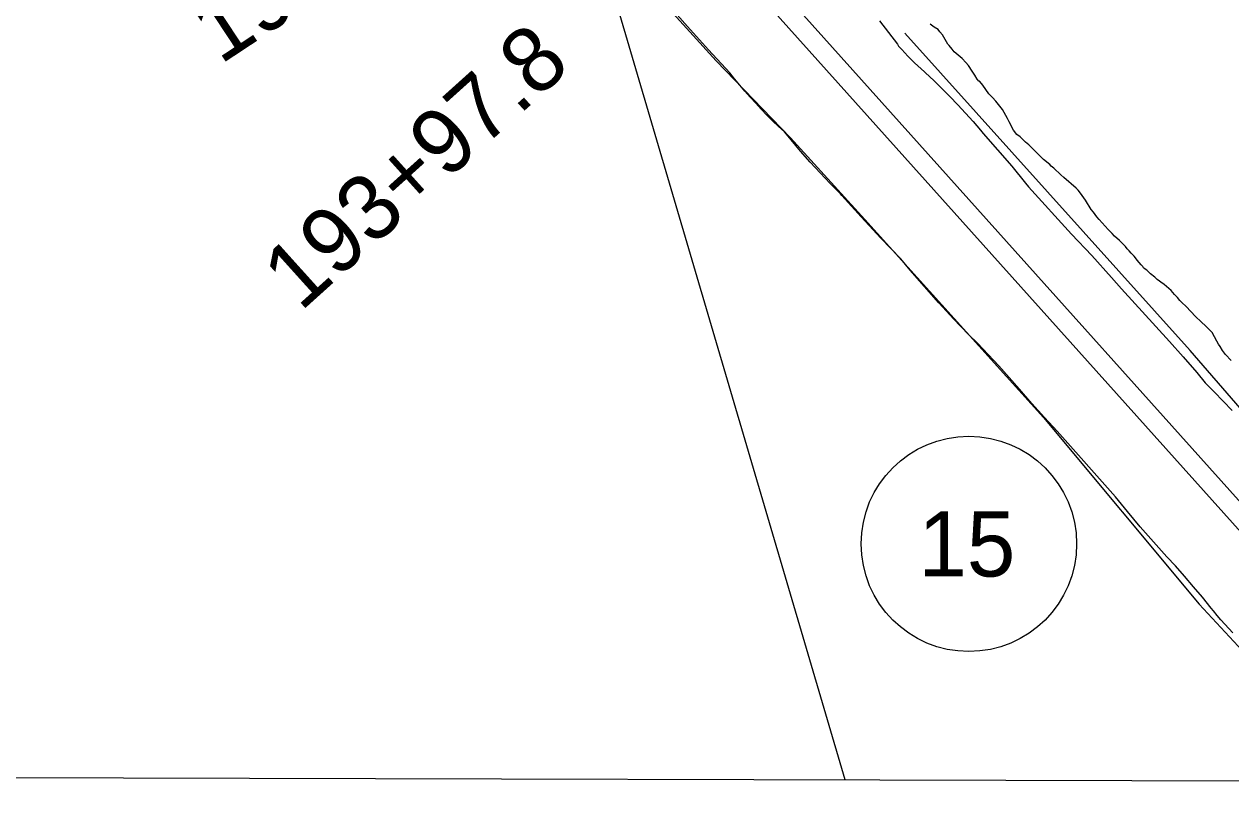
# Model space of a CAD drawing. Extents: x 3172231 to 3210228, y 940198 to 965780.
# Drawn here: x 3188013 to 3189862, y 945652 to 946857 of the extents above; entities that cross this region are included whole.
import ezdxf

# ---------------------------------------------------------------- set-up
doc = ezdxf.new("R2010")
doc.units = 0
for name, color, linetype in [('V-GRID-FRAM', 7, 'Continuous'), ('V-LEVE-TOET', 7, 'Continuous'), ('V-ROAD-IDEN', 7, 'Continuous'), ('V-SITE-VEGE', 7, 'Continuous'), ('V-SURV-IDEN', 7, 'Continuous'), ('V-SURV-LINE', 7, 'Continuous'), ('V-TOPO-BNDY', 7, 'Continuous'), ('V-TOPO-SHOR', 7, 'Continuous')]:
    doc.layers.add(name, color=color, linetype=linetype)

msp = doc.modelspace()

# ---------------------------------------------------------------- linework, layer by layer
at = {"layer": 'V-GRID-FRAM'}
msp.add_lwpolyline([(3176539.592, 963919.479), (3207827.662, 963842.116), (3207790.623, 945652.442), (3176486.679, 945729.845), (3176539.592, 963919.479)], dxfattribs=at)
at = {"layer": 'V-LEVE-TOET'}
for points in [[(3189865.016, 945923.694), (3189858.825, 945930.252), (3189852.751, 945936.916), (3189846.795, 945943.684), (3189840.956, 945950.556), (3189835.238, 945957.527), (3189831.896, 945961.721), (3189831.896, 945961.721), (3189818.602, 945978.21), (3189805.024, 945994.463), (3189791.165, 946010.478), (3189777.028, 946026.248), (3189763.816, 946040.502), (3189763.816, 946040.502), (3189743.297, 946063.247), (3189723.176, 946086.346), (3189703.458, 946109.79), (3189685.284, 946132.156), (3189685.284, 946132.156), (3189595.733, 946232.725), (3189595.733, 946232.725), (3189576.504, 946254.049), (3189557.261, 946275.497), (3189538.072, 946296.991), (3189538.072, 946296.991), (3189522.415, 946315.061), (3189506.457, 946332.864), (3189490.197, 946350.395), (3189473.646, 946367.647), (3189460.297, 946381.145), (3189460.297, 946381.145), (3189437.312, 946405.177), (3189414.749, 946429.605), (3189392.614, 946454.423), (3189370.914, 946479.621), (3189356.371, 946497.017), (3189356.371, 946497.017), (3189325.692, 946528.792), (3189295.57, 946561.099), (3189266.019, 946593.924), (3189263.754, 946596.489), (3189263.754, 946596.489), (3189248.071, 946612.514), (3189232.668, 946628.814), (3189217.553, 946645.378), (3189202.728, 946662.203), (3189188.199, 946679.285), (3189178.052, 946691.585), (3189178.052, 946691.585), (3189168.942, 946700.019), (3189159.982, 946708.61), (3189151.172, 946717.357), (3189142.517, 946726.256), (3189134.017, 946735.304), (3189125.678, 946744.5), (3189117.5, 946753.838), (3189109.487, 946763.319), (3189101.639, 946772.938), (3189094.348, 946782.193), (3189094.348, 946782.193), (3189061.516, 946817.458), (3189029.289, 946853.275), (3189013.872, 946870.853)], [(3189323.783, 946861.932), (3189337.523, 946843.893), (3189351.112, 946825.731), (3189353.043, 946823.122), (3189353.043, 946823.122), (3189357.684, 946817.861), (3189362.412, 946812.677), (3189367.231, 946807.576), (3189372.134, 946802.554), (3189377.123, 946797.616), (3189382.194, 946792.765), (3189387.347, 946787.999), (3189392.58, 946783.321), (3189394.173, 946781.929), (3189394.173, 946781.929), (3189406.838, 946770.052), (3189419.294, 946757.957), (3189431.539, 946745.648), (3189443.567, 946733.127), (3189455.375, 946720.399), (3189466.961, 946707.468), (3189478.319, 946694.336), (3189482.737, 946689.103), (3189482.737, 946689.103), (3189504.712, 946664.157), (3189526.257, 946638.837), (3189547.363, 946613.151), (3189551.916, 946607.49), (3189551.916, 946607.49), (3189617.8, 946534.844), (3189617.8, 946534.844), (3189648.793, 946501.891), (3189679.205, 946468.405), (3189694.645, 946450.945), (3189694.645, 946450.945), (3189746.851, 946393.356), (3189746.851, 946393.356), (3189768.199, 946370.18), (3189789.144, 946346.641), (3189809.679, 946322.743), (3189822.707, 946307.143), (3189822.707, 946307.143), (3189836.649, 946293.081), (3189850.432, 946278.86), (3189864.048, 946264.479)]]:
    msp.add_lwpolyline(points, dxfattribs=at)
at = {"layer": 'V-ROAD-IDEN'}
msp.add_circle((3189460.656, 946060.116), 165, dxfattribs=at)
at = {"layer": 'V-SITE-VEGE'}
for p, q in [((3189407.581, 946852.134), (3189401.085, 946856.689)), ((3189413.363, 946848.329), (3189407.581, 946852.134)), ((3189416.22, 946844.962), (3189413.363, 946848.329)), ((3189420.142, 946840.098), (3189416.22, 946844.962)), ((3189428.614, 946825.959), (3189420.142, 946840.098)), ((3189430.404, 946824.081), (3189428.614, 946825.959)), ((3189435.033, 946818.103), (3189430.404, 946824.081)), ((3189438.248, 946814.359), (3189435.033, 946818.103)), ((3189450.114, 946804.172), (3189438.248, 946814.359)), ((3189456.203, 946797.793), (3189450.114, 946804.172)), ((3189460.133, 946793.297), (3189456.203, 946797.793)), ((3189465.802, 946784.726), (3189460.133, 946793.297)), ((3189469.689, 946778.398), (3189465.802, 946784.726)), ((3189473.584, 946772.438), (3189469.689, 946778.398)), ((3189476.083, 946769.442), (3189473.584, 946772.438)), ((3189476.806, 946769.057), (3189476.083, 946769.442)), ((3189480.029, 946765.68), (3189476.806, 946769.057)), ((3189481.805, 946763.071), (3189480.029, 946765.68)), ((3189491.402, 946750.005), (3189481.805, 946763.071)), ((3189496.772, 946744.377), (3189491.402, 946750.005)), ((3189501.769, 946738.386), (3189496.772, 946744.377)), ((3189512.109, 946725.668), (3189501.769, 946738.386)), ((3189517.401, 946716.741), (3189512.109, 946725.668)), ((3189519.867, 946712.278), (3189517.401, 946716.741)), ((3189522.312, 946707.085), (3189519.867, 946712.278)), ((3189528.976, 946694.086), (3189522.312, 946707.085)), ((3189533.963, 946687.733), (3189528.976, 946694.086)), ((3189539.012, 946683.946), (3189533.963, 946687.733)), ((3189547.623, 946675.672), (3189539.012, 946683.946)), ((3189552.661, 946671.517), (3189547.623, 946675.672)), ((3189561.621, 946662.502), (3189552.661, 946671.517)), ((3189567.708, 946656.12), (3189561.621, 946662.502)), ((3189574.888, 946649.349), (3189567.708, 946656.12)), ((3189584.606, 946641.416), (3189574.888, 946649.349)), ((3189586.757, 946639.165), (3189584.606, 946641.416)), ((3189590.719, 946636.136), (3189586.757, 946639.165)), ((3189601.48, 946625.609), (3189590.719, 946636.136)), ((3189606.159, 946621.831), (3189601.48, 946625.609)), ((3189625.216, 946605.24), (3189606.159, 946621.831)), ((3189628.079, 946602.237), (3189625.216, 946605.24)), ((3189631.645, 946597.75), (3189628.079, 946602.237)), ((3189639.462, 946586.928), (3189631.645, 946597.75)), ((3189647.934, 946572.789), (3189639.462, 946586.928)), ((3189651.498, 946568.3), (3189647.934, 946572.789)), ((3189656.466, 946561.214), (3189651.498, 946568.3)), ((3189660.407, 946557.083), (3189656.466, 946561.214)), ((3189673.995, 946542.09), (3189660.407, 946557.083)), ((3189677.227, 946539.079), (3189673.995, 946542.09)), ((3189680.084, 946535.708), (3189677.227, 946539.079)), ((3189683.664, 946531.956), (3189680.084, 946535.708)), ((3189691.209, 946525.175), (3189683.664, 946531.956)), ((3189700.527, 946515.783), (3189691.209, 946525.175)), ((3189703.374, 946512.047), (3189700.527, 946515.783)), ((3189706.239, 946509.045), (3189703.374, 946512.047)), ((3189709.094, 946505.676), (3189706.239, 946509.045)), ((3189713.757, 946501.164), (3189709.094, 946505.676)), ((3189715.897, 946498.545), (3189713.757, 946501.164)), ((3189718.746, 946494.809), (3189715.897, 946498.545)), ((3189724.814, 946487.697), (3189718.746, 946494.809)), ((3189727.331, 946485.436), (3189724.814, 946487.697)), ((3189728.38, 946483.212), (3189727.331, 946485.436)), ((3189730.534, 946481.325), (3189728.38, 946483.212)), ((3189733.06, 946479.431), (3189730.534, 946481.325)), ((3189737.375, 946475.661), (3189733.06, 946479.431)), ((3189739.165, 946473.783), (3189737.375, 946475.661)), ((3189745.653, 946468.861), (3189739.165, 946473.783)), ((3189749.243, 946465.476), (3189745.653, 946468.861)), ((3189752.847, 946462.824), (3189749.243, 946465.476)), ((3189754.648, 946461.312), (3189752.847, 946462.824)), ((3189759.696, 946457.526), (3189754.648, 946461.312)), ((3189770.489, 946448.467), (3189759.696, 946457.526)), ((3189775.484, 946442.479), (3189770.489, 946448.467)), ((3189780.139, 946437.601), (3189775.484, 946442.479)), ((3189784.069, 946433.105), (3189780.139, 946437.601)), ((3189786.934, 946430.103), (3189784.069, 946433.105)), ((3189793.396, 946424.08), (3189786.934, 946430.103)), ((3189808.078, 946408.693), (3189793.396, 946424.08)), ((3189816.321, 946400.427), (3189808.078, 946408.693)), ((3189823.868, 946393.646), (3189816.321, 946400.427)), ((3189826.014, 946391.394), (3189823.868, 946393.646)), ((3189828.529, 946389.135), (3189826.014, 946391.394)), ((3189830.669, 946386.515), (3189828.529, 946389.135)), ((3189833.543, 946383.88), (3189830.669, 946386.515)), ((3189840.575, 946370.875), (3189833.543, 946383.88)), ((3189843.031, 946366.046), (3189840.575, 946370.875)), ((3189845.519, 946362.685), (3189843.031, 946366.046)), ((3189849.406, 946356.356), (3189845.519, 946362.685)), ((3189854.035, 946350.378), (3189849.406, 946356.356)), ((3189862.62, 946341.005), (3189854.035, 946350.378))]:
    msp.add_line(p, q, dxfattribs=at)
at = {"layer": 'V-SURV-LINE'}
for points in [[(3189074.013, 947019.772), (3190260.278, 945695.789)], [(3190219.909, 945695.889), (3189051.684, 946999.737)]]:
    msp.add_lwpolyline(points, dxfattribs=at)
at = {"layer": 'V-TOPO-BNDY'}
msp.add_line((3189271.114, 945698.234), (3188711.943, 947598.102), dxfattribs=at)
at = {"layer": 'V-TOPO-SHOR'}
for points in [[(3188856.461, 947040.104), (3189073.439, 946800.597), (3189187.283, 946682.613), (3189301.109, 946557.497), (3189574.995, 946253.648), (3189813.258, 945967.721), (3190065.824, 945696.025)], [(3190372.56, 945695.267), (3189799.953, 946356.527), (3189362.448, 946842.683)]]:
    msp.add_lwpolyline(points, dxfattribs=at)

# ---------------------------------------------------------------- texts
at = {"layer": 'V-ROAD-IDEN'}
msp.add_text('15', height=99.9998, dxfattribs=at).set_placement((3189383.098, 946010.116))
at = {"layer": 'V-SURV-IDEN'}
for s, rotation, p in [('191+40.9', 33.431944, (3188313.36, 946793.707)), ('193+97.8', 42.006389, (3188436.435, 946414.825))]:
    msp.add_text(s, height=100, rotation=rotation, dxfattribs=at).set_placement(p)

doc.saveas('drawing.dxf')
